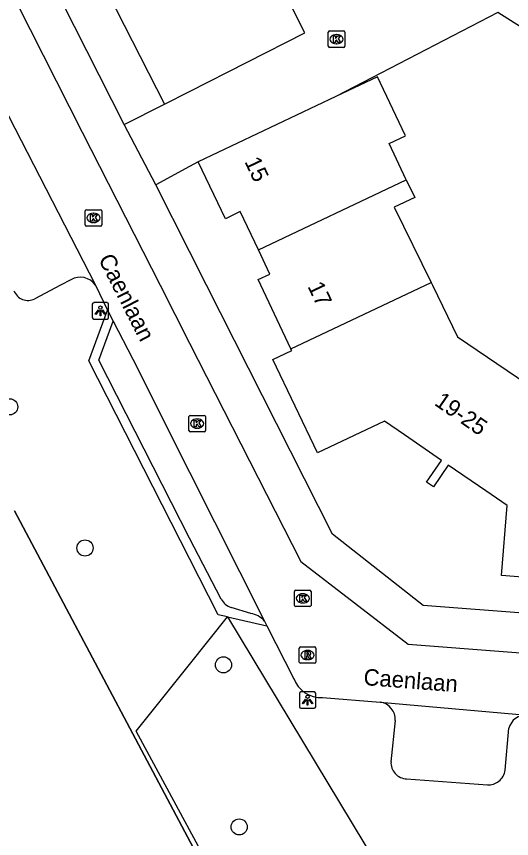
# Model space of a CAD drawing. Extents: x 158474 to 159560, y 388525 to 389605.
# Drawn here: x 158989.49 to 159019.56, y 388966.38 to 389016.33 of the extents above; entities that cross this region are included whole.
import ezdxf

# ---------------------------------------------------------------- set-up
doc = ezdxf.new("R2010")
doc.units = 0
for name, color, linetype in [('IMGEO_Boom', 7, 'Continuous'), ('IMGEO_Groenvoorziening', 7, 'Continuous'), ('IMGEO_Hek', 7, 'Continuous'), ('IMGEO_Kolk', 7, 'Continuous'), ('IMGEO_Lichtpunt', 7, 'Continuous'), ('IMGEO_Openbare_ruimte_label', 7, 'Continuous'), ('IMGEO_Pand', 7, 'Continuous'), ('IMGEO_Pand_nummerreeks', 7, 'Continuous'), ('IMGEO_Parkeervlak_open', 7, 'Continuous'), ('IMGEO_Rijbaan_lokaal_open', 7, 'Continuous'), ('IMGEO_Rioolput', 7, 'Continuous'), ('IMGEO_Voetpad_open', 7, 'Continuous')]:
    doc.layers.add(name, color=color, linetype=linetype)

msp = doc.modelspace()

# ---------------------------------------------------------------- linework, layer by layer
at = {"layer": 'IMGEO_Boom'}
for centre in [(158989.086, 388992.614), (158993.657, 388984.038), (159002.064, 388976.937), (159003.018, 388967.091)]:
    msp.add_circle(centre, 0.489, dxfattribs=at)
at = {"layer": 'IMGEO_Groenvoorziening'}
for points in [[(159002.847, 388961.622), (159001.99, 388962.516), (158989.382, 388986.291)], [(159002.847, 388961.622), (159000, 388966.916), (158996.769, 388972.909), (159000, 388976.968), (159002.305, 388979.849)], [(159002.305, 388979.849), (159014.438, 388959.738)]]:
    msp.add_lwpolyline(points, dxfattribs=at)
at = {"layer": 'IMGEO_Hek'}
msp.add_lwpolyline([(158989.382, 388986.291), (159001.99, 388962.516), (159002.847, 388961.622)], dxfattribs=at)
at = {"layer": 'IMGEO_Kolk'}
for p, q in [((159008.43, 389014.524), (159008.43, 389015.376)), ((159008.505, 389015.45), (159009.357, 389015.45)), ((159008.918, 389015.23), (159008.943, 389015.23)), ((159009.431, 389015.376), (159009.431, 389014.524)), ((159008.941, 389014.67), (159008.916, 389014.67)), ((159009.357, 389014.45), (159008.505, 389014.45)), ((158993.672, 389003.666), (158993.672, 389004.518)), ((158993.747, 389004.592), (158994.599, 389004.592)), ((158994.16, 389004.372), (158994.185, 389004.372)), ((158994.673, 389004.518), (158994.673, 389003.666)), ((158994.183, 389003.812), (158994.158, 389003.812)), ((158994.599, 389003.592), (158993.747, 389003.592)), ((158999.97, 388991.168), (158999.97, 388992.02)), ((159000.045, 388992.094), (159000.897, 388992.094)), ((159000.458, 388991.874), (159000.483, 388991.874)), ((159000.971, 388992.02), (159000.971, 388991.168)), ((159000.481, 388991.314), (159000.456, 388991.314)), ((159000.897, 388991.094), (159000.045, 388991.094)), ((159006.379, 388980.552), (159006.379, 388981.404)), ((159006.454, 388981.478), (159007.306, 388981.478)), ((159006.867, 388981.258), (159006.892, 388981.258)), ((159007.38, 388981.404), (159007.38, 388980.552)), ((159006.89, 388980.698), (159006.865, 388980.698)), ((159007.306, 388980.478), (159006.454, 388980.478))]:
    msp.add_line(p, q, dxfattribs=at)
for points in [[(159008.43, 389014.524), (159008.43, 389015.376)], [(159008.505, 389015.45), (159009.357, 389015.45)], [(159008.751, 389015.15), (159008.874, 389015.15), (159008.874, 389014.999), (159009.004, 389015.15), (159009.168, 389015.15), (159009.022, 389014.999), (159009.175, 389014.75), (159009.023, 389014.75), (159008.938, 389014.914), (159008.874, 389014.847), (159008.874, 389014.75), (159008.751, 389014.75), (159008.751, 389015.15)], [(159009.431, 389015.376), (159009.431, 389014.524)], [(159009.357, 389014.45), (159008.505, 389014.45)], [(158993.672, 389003.666), (158993.672, 389004.518)], [(158993.747, 389004.592), (158994.599, 389004.592)], [(158993.993, 389004.292), (158994.116, 389004.292), (158994.116, 389004.141), (158994.246, 389004.292), (158994.41, 389004.292), (158994.264, 389004.141), (158994.417, 389003.892), (158994.265, 389003.892), (158994.18, 389004.056), (158994.116, 389003.989), (158994.116, 389003.892), (158993.993, 389003.892), (158993.993, 389004.292)], [(158994.673, 389004.518), (158994.673, 389003.666)], [(158994.599, 389003.592), (158993.747, 389003.592)], [(158999.97, 388991.168), (158999.97, 388992.02)], [(159000.045, 388992.094), (159000.897, 388992.094)], [(159000.291, 388991.794), (159000.414, 388991.794), (159000.414, 388991.643), (159000.544, 388991.794), (159000.708, 388991.794), (159000.562, 388991.643), (159000.715, 388991.394), (159000.563, 388991.394), (159000.478, 388991.558), (159000.414, 388991.491), (159000.414, 388991.394), (159000.291, 388991.394), (159000.291, 388991.794)], [(159000.971, 388992.02), (159000.971, 388991.168)], [(159000.897, 388991.094), (159000.045, 388991.094)], [(159006.379, 388980.552), (159006.379, 388981.404)], [(159006.454, 388981.478), (159007.306, 388981.478)], [(159006.7, 388981.178), (159006.823, 388981.178), (159006.823, 388981.027), (159006.953, 388981.178), (159007.117, 388981.178), (159006.971, 388981.027), (159007.124, 388980.778), (159006.972, 388980.778), (159006.887, 388980.942), (159006.823, 388980.875), (159006.823, 388980.778), (159006.7, 388980.778), (159006.7, 388981.178)], [(159007.38, 388981.404), (159007.38, 388980.552)], [(159007.306, 388980.478), (159006.454, 388980.478)]]:
    msp.add_lwpolyline(points, dxfattribs=at)
for centre, start, end in [((159008.507, 389015.374), 91.552, 178.448), ((159008.507, 389015.374), 91.552, 178.448), ((159009.355, 389015.374), 1.552, 88.448), ((159009.355, 389015.374), 1.552, 88.448), ((159008.507, 389014.526), 181.552, 268.448), ((159008.507, 389014.526), 181.552, 268.448), ((159009.355, 389014.526), 271.552, 358.448), ((159009.355, 389014.526), 271.552, 358.448), ((158993.749, 389004.516), 91.552, 178.448), ((158993.749, 389004.516), 91.552, 178.448), ((158994.597, 389004.516), 1.552, 88.448), ((158994.597, 389004.516), 1.552, 88.448), ((158993.749, 389003.668), 181.552, 268.448), ((158993.749, 389003.668), 181.552, 268.448), ((158994.597, 389003.668), 271.552, 358.448), ((158994.597, 389003.668), 271.552, 358.448), ((159000.047, 388992.018), 91.552, 178.448), ((159000.047, 388992.018), 91.552, 178.448), ((159000.895, 388992.018), 1.552, 88.448), ((159000.895, 388992.018), 1.552, 88.448), ((159000.047, 388991.17), 181.552, 268.448), ((159000.047, 388991.17), 181.552, 268.448), ((159000.895, 388991.17), 271.552, 358.448), ((159000.895, 388991.17), 271.552, 358.448), ((159006.456, 388981.402), 91.552, 178.448), ((159006.456, 388981.402), 91.552, 178.448), ((159007.304, 388981.402), 1.552, 88.448), ((159007.304, 388981.402), 1.552, 88.448), ((159006.456, 388980.554), 181.552, 268.448), ((159006.456, 388980.554), 181.552, 268.448), ((159007.304, 388980.554), 271.552, 358.448), ((159007.304, 388980.554), 271.552, 358.448)]:
    msp.add_arc(centre, 0.0765, start, end, dxfattribs=at)
for centre, major_axis, ratio, start_param, end_param in [((159008.917, 389014.95), (-0.387, 0.002), 0.722429, 4.712389, 7.853982), ((159008.942, 389014.95), (-0.39, 0.002), 0.717154, 1.570796, 4.712389), ((158994.159, 389004.092), (-0.387, 0.002), 0.722429, 4.712389, 7.853982), ((158994.184, 389004.092), (-0.39, 0.002), 0.717154, 1.570796, 4.712389), ((159000.457, 388991.594), (-0.387, 0.002), 0.722429, 4.712389, 7.853982), ((159000.482, 388991.594), (-0.39, 0.002), 0.717154, 1.570796, 4.712389), ((159006.866, 388980.978), (-0.387, 0.002), 0.722429, 4.712389, 7.853982), ((159006.891, 388980.978), (-0.39, 0.002), 0.717154, 1.570796, 4.712389)]:
    msp.add_ellipse(centre, major_axis=major_axis, ratio=ratio, start_param=start_param, end_param=end_param, dxfattribs=at)
at = {"layer": 'IMGEO_Lichtpunt'}
for p, q in [((158994.096, 388998.848), (158994.096, 388998.041)), ((158994.096, 388998.848), (158994.096, 388998.041)), ((158994.998, 388998.943), (158994.19, 388998.943)), ((158994.998, 388998.943), (158994.19, 388998.943)), ((158995.092, 388998.041), (158995.092, 388998.848)), ((158995.092, 388998.041), (158995.092, 388998.848)), ((158994.19, 388997.947), (158994.998, 388997.947)), ((158994.19, 388997.947), (158994.998, 388997.947)), ((159006.674, 388975.199), (159006.674, 388974.392)), ((159006.674, 388975.199), (159006.674, 388974.392)), ((159007.576, 388975.294), (159006.768, 388975.294)), ((159007.576, 388975.294), (159006.768, 388975.294)), ((159007.67, 388974.392), (159007.67, 388975.199)), ((159007.67, 388974.392), (159007.67, 388975.199)), ((159006.768, 388974.298), (159007.576, 388974.298)), ((159006.768, 388974.298), (159007.576, 388974.298))]:
    msp.add_line(p, q, dxfattribs=at)
for points in [[(158994.47, 388998.512), (158994.509, 388998.484), (158994.321, 388998.222), (158994.283, 388998.249), (158994.47, 388998.512)], [(158994.572, 388998.464), (158994.619, 388998.464), (158994.619, 388998.142), (158994.572, 388998.142), (158994.572, 388998.464)], [(158994.682, 388998.484), (158994.72, 388998.511), (158994.907, 388998.249), (158994.868, 388998.221), (158994.682, 388998.484)], [(159007.048, 388974.863), (159007.087, 388974.835), (159006.899, 388974.573), (159006.861, 388974.6), (159007.048, 388974.863)], [(159007.15, 388974.815), (159007.197, 388974.815), (159007.197, 388974.493), (159007.15, 388974.493), (159007.15, 388974.815)], [(159007.26, 388974.835), (159007.298, 388974.862), (159007.485, 388974.6), (159007.446, 388974.572), (159007.26, 388974.835)]]:
    msp.add_lwpolyline(points, dxfattribs=at)
for centre in [(158994.595, 388998.646), (159007.173, 388974.997)]:
    msp.add_circle(centre, 0.0994, dxfattribs=at)
for centre, start, end in [((158994.19, 388998.848), 90, 180), ((158994.19, 388998.848), 90, 180), ((158994.998, 388998.848), 0, 90), ((158994.998, 388998.848), 0, 90), ((158994.19, 388998.041), 180, 270), ((158994.19, 388998.041), 180, 270), ((158994.998, 388998.041), 270, 0), ((158994.998, 388998.041), 270, 360), ((159006.768, 388975.199), 90, 180), ((159006.768, 388975.199), 90, 180), ((159007.576, 388975.199), 0, 90), ((159007.576, 388975.199), 0, 90), ((159006.768, 388974.392), 180, 270), ((159006.768, 388974.392), 180, 270), ((159007.576, 388974.392), 270, 0), ((159007.576, 388974.392), 270, 360)]:
    msp.add_arc(centre, 0.0946, start, end, dxfattribs=at)
at = {"layer": 'IMGEO_Pand'}
for points in [[(159005.093, 389037.803), (159004.425, 389039.145), (159001.238, 389037.526), (159001.579, 389036.855), (159000, 389036.053), (158997.187, 389034.623), (158996.447, 389036.081), (158993.211, 389034.437), (158993.846, 389033.187), (158991.21, 389031.847), (158992.45, 389029.407), (158989.799, 389028.06), (158992.205, 389023.324), (158991.627, 389023.03), (158993.483, 389019.378), (158994.068, 389019.675), (158998.474, 389011.004)], [(158998.474, 389011.004), (159000, 389011.78), (159007.011, 389015.342), (159006.28, 389016.78)], [(159013.165, 389006.415), (159012.125, 389008.605), (159013.119, 389009.077), (159013.095, 389009.126), (159011.414, 389012.669), (159008.893, 389011.472)], [(159008.893, 389011.472), (159000.537, 389007.505)], [(159004.189, 389002.152), (159003.086, 389004.475), (159002.179, 389004.045), (159000.537, 389007.505)], [(159004.189, 389002.152), (159013.165, 389006.415)], [(159013.165, 389006.415), (159013.682, 389005.326), (159012.439, 389004.736), (159014.67, 389000.177)], [(159006.165, 388996.138), (159004.332, 389000), (159004.169, 389000.343), (159004.886, 389000.683), (159004.189, 389002.152)], [(159006.165, 388996.138), (159014.67, 389000.177)], [(159014.67, 389000.177), (159014.757, 389000), (159016.286, 388996.876), (159022.316, 388992.767), (159026.461, 388992.433)], [(159025.729, 388983.256), (159025.414, 388983.281), (159025.3, 388981.862), (159018.951, 388982.373), (159019.292, 388986.61), (159017.996, 388987.504), (159015.716, 388989.077), (159014.809, 388987.763), (159014.397, 388988.047), (159015.303, 388989.361), (159013.056, 388990.912), (159011.844, 388991.748), (159007.766, 388989.812), (159005.066, 388995.499), (159006.21, 388996.043), (159006.165, 388996.138)]]:
    msp.add_lwpolyline(points, dxfattribs=at)
at = {"layer": 'IMGEO_Parkeervlak_open'}
for points in [[(158992.793, 389000.334), (158992.159, 389000), (158990.605, 388999.183)], [(159012.493, 388973.562), (159012.238, 388971.052)], [(159019.169, 388970.542), (159019.395, 388973.083)], [(159013.187, 388970.011), (159018.089, 388969.648)]]:
    msp.add_lwpolyline(points, dxfattribs=at)
for centre, radius, start, end in [((158993.367, 388999.355), 1.135, 34.7068, 120.3725), ((158990.186, 388999.98), 0.9, 200.7507, 297.7294), ((159011.449, 388973.629), 1.047, 356.313, 82.5082), ((159020.416, 388972.838), 1.05, 85.5733, 166.5186), ((159013.223, 388970.997), 0.986, 176.7799, 267.9262), ((159018.151, 388970.671), 1.026, 308.4442, 352.8), ((159018.152, 388970.676), 1.03, 266.5056, 308.2398)]:
    msp.add_arc(centre, radius, start, end, dxfattribs=at)
at = {"layer": 'IMGEO_Rijbaan_lokaal_open'}
for points in [[(158984.014, 389027.992), (158993.474, 389009.309), (158998.214, 389000), (159000, 388996.492), (159006.761, 388983.213), (159013.283, 388978.189), (159025.348, 388977.262), (159025.292, 388976.52)], [(158984.481, 389019.104), (158994.3, 389000.001)], [(159021.644, 389014.727), (159018.722, 389016.57), (159008.893, 389011.472)], [(158996.04, 389009.776), (158998.474, 389011.004)], [(158997.951, 389006.112), (158996.04, 389009.776)], [(159000.537, 389007.505), (159000, 389007.216), (158997.951, 389006.112)], [(158994.3, 389000.001), (158995.013, 388998.492)], [(158995.013, 388998.492), (158995.361, 388997.817)], [(158995.361, 388997.817), (158996.553, 388995.503), (159000, 388988.648), (159004.55, 388979.598)], [(159004.55, 388979.598), (159004.7, 388979.3)], [(159004.7, 388979.3), (159006.328, 388976.099)], [(159008.072, 388974.947), (159011.585, 388974.667)], [(159011.585, 388974.667), (159020.497, 388973.885)]]:
    msp.add_lwpolyline(points, dxfattribs=at)
msp.add_arc((159008.008, 388976.747), 1.801, 201.0847, 272.0217, dxfattribs=at)
at = {"layer": 'IMGEO_Rioolput'}
for p, q in [((159006.669, 388977.108), (159006.669, 388977.96)), ((159006.744, 388978.034), (159007.596, 388978.034)), ((159007.157, 388977.814), (159007.182, 388977.814)), ((159007.67, 388977.96), (159007.67, 388977.108)), ((159007.18, 388977.254), (159007.155, 388977.254)), ((159007.596, 388977.034), (159006.744, 388977.034))]:
    msp.add_line(p, q, dxfattribs=at)
for points in [[(159006.669, 388977.108), (159006.669, 388977.96)], [(159006.744, 388978.034), (159007.596, 388978.034)], [(159007.258, 388977.732), (159007.006, 388977.734), (159007.006, 388977.334)], [(159007.184, 388977.653), (159007.13, 388977.653), (159007.13, 388977.572)], [(159007.67, 388977.96), (159007.67, 388977.108)], [(159007.006, 388977.334), (159007.13, 388977.334), (159007.13, 388977.496), (159007.141, 388977.496)], [(159007.13, 388977.572), (159007.182, 388977.572)], [(159007.188, 388977.467), (159007.259, 388977.334), (159007.399, 388977.334), (159007.334, 388977.46)], [(159007.596, 388977.034), (159006.744, 388977.034)]]:
    msp.add_lwpolyline(points, dxfattribs=at)
for centre, radius, start, end in [((159006.746, 388977.958), 0.0765, 91.552, 178.448), ((159006.746, 388977.958), 0.0765, 91.552, 178.448), ((159007.19, 388977.557), 0.0964, 77.0061, 93.1865), ((159007.204, 388977.614), 0.0378, 276.6634, 79.6772), ((159007.257, 388977.622), 0.109, 350.3612, 89.416), ((159007.594, 388977.958), 0.0765, 1.552, 88.448), ((159007.594, 388977.958), 0.0765, 1.552, 88.448), ((159007.14, 388977.443), 0.0533, 26.0293, 88.6989), ((159007.166, 388977.761), 0.19, 274.7715, 282.9687), ((159007.255, 388977.622), 0.112, 277.5842, 350.9817), ((159007.239, 388977.407), 0.108, 29.5134, 73.7905), ((159006.746, 388977.11), 0.0765, 181.552, 268.448), ((159006.746, 388977.11), 0.0765, 181.552, 268.448), ((159007.594, 388977.11), 0.0765, 271.552, 358.448), ((159007.594, 388977.11), 0.0765, 271.552, 358.448)]:
    msp.add_arc(centre, radius, start, end, dxfattribs=at)
for centre, major_axis, ratio, start_param, end_param in [((159007.156, 388977.534), (-0.387, 0.002), 0.722429, 4.712389, 7.853982), ((159007.181, 388977.534), (-0.39, 0.002), 0.717154, 1.570796, 4.712389)]:
    msp.add_ellipse(centre, major_axis=major_axis, ratio=ratio, start_param=start_param, end_param=end_param, dxfattribs=at)
at = {"layer": 'IMGEO_Voetpad_open'}
for points in [[(158996.04, 389009.776), (158986.191, 389029.159)], [(159056.664, 388980.857), (159047.704, 388977.974), (159014.183, 388980.546), (159008.681, 388984.868), (159001.038, 389000), (159000, 389002.056), (158997.951, 389006.112)], [(159002.305, 388979.849), (159001.74, 388979.979), (159000, 388983.398), (158993.883, 388995.418), (158995.013, 388998.492)], [(159001.929, 388980.932), (159000, 388984.632), (158994.492, 388995.454), (158995.361, 388997.817)], [(159003.721, 388980.063), (159002.531, 388980.424)], [(159002.305, 388979.849), (159004.7, 388979.3)]]:
    msp.add_lwpolyline(points, dxfattribs=at)
for centre, radius, start, end in [((159002.822, 388981.38), 0.999, 206.6199, 253.0611), ((159003.536, 388978.761), 1.315, 39.527, 81.8954)]:
    msp.add_arc(centre, radius, start, end, dxfattribs=at)

# ---------------------------------------------------------------- texts
at = {"layer": 'IMGEO_Openbare_ruimte_label'}
for rotation, p in [(297.0007, (158994.445, 389001.595)), (355.6408, (159010.546, 388975.713))]:
    msp.add_text('Caenlaan', height=1, rotation=rotation, dxfattribs=at).set_placement(p)
at = {"layer": 'IMGEO_Pand_nummerreeks'}
for s, rotation, p in [('15', 295.3704, (159003.321, 389007.52)), ('17', 295.3914, (159007.152, 388999.94)), ('19-25', 325.4002, (159014.814, 388992.761))]:
    msp.add_text(s, height=1, rotation=rotation, dxfattribs=at).set_placement(p)

doc.saveas('drawing.dxf')
